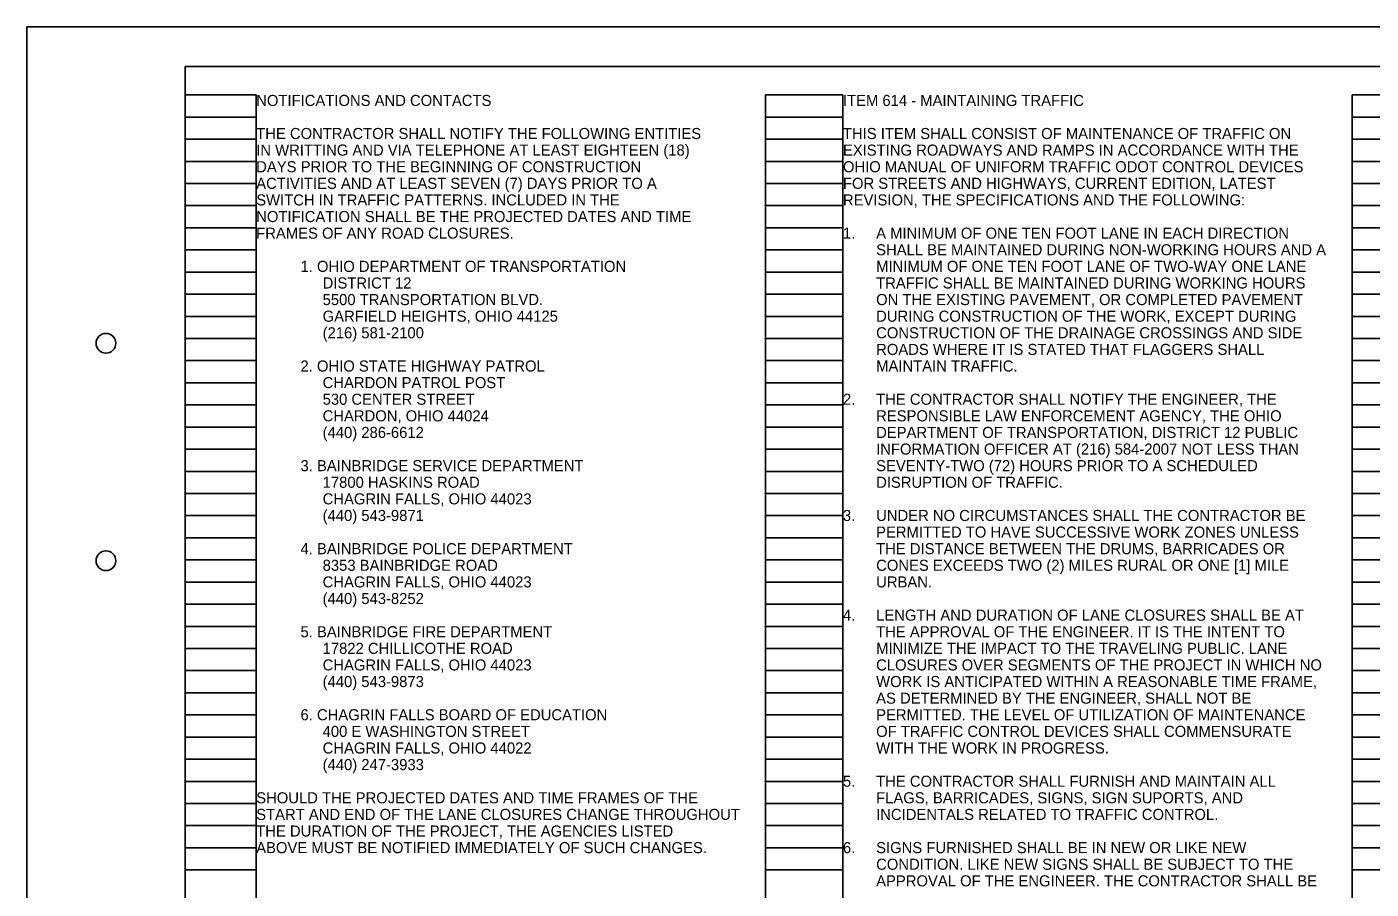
# Model space of a CAD drawing. Extents: x -16.4 to 17.6, y -12.9 to 9.1.
# Drawn here: x -16.37 to 0.63, y -1.81 to 9.09 of the extents above; entities that cross this region are included whole.
import ezdxf

# ---------------------------------------------------------------- set-up
doc = ezdxf.new("R2010")
doc.units = 0
for name, color, linetype in [('SH_Border', 7, 'Continuous'), ('SH_Cut_Line', 7, 'Continuous'), ('SH_Data', 7, 'Continuous'), ('SH_Text', 7, 'Continuous'), ('TX_P_1', 7, 'Continuous')]:
    doc.layers.add(name, color=color, linetype=linetype)

# ---------------------------------------------------------------- blocks, each defined once
blk = doc.blocks.new('4COL')
at = {"layer": 'SH_Data'}
for p, q in [((2, 0.98), (2, 21.14)), ((2, 21.14), (2.9, 21.14)), ((2.9, 0.98), (2.9, 21.14)), ((9.34, 0.98), (9.34, 21.14)), ((9.34, 21.14), (10.32, 21.14)), ((10.32, 0.98), (10.32, 21.14)), ((16.76, 0.98), (16.76, 21.14)), ((16.76, 21.14), (17.74, 21.14)), ((2, 20.86), (2.9, 20.86)), ((9.34, 20.86), (10.32, 20.86)), ((16.76, 20.86), (17.74, 20.86)), ((2, 20.58), (2.9, 20.58)), ((9.34, 20.58), (10.32, 20.58)), ((16.76, 20.58), (17.74, 20.58)), ((2, 20.3), (2.9, 20.3)), ((9.34, 20.3), (10.32, 20.3)), ((16.76, 20.3), (17.74, 20.3)), ((2, 20.02), (2.9, 20.02)), ((9.34, 20.02), (10.32, 20.02)), ((16.76, 20.02), (17.74, 20.02)), ((2, 19.74), (2.9, 19.74)), ((9.34, 19.74), (10.32, 19.74)), ((16.76, 19.74), (17.74, 19.74)), ((2, 19.46), (2.9, 19.46)), ((9.34, 19.46), (10.32, 19.46)), ((16.76, 19.46), (17.74, 19.46)), ((2, 19.18), (2.9, 19.18)), ((9.34, 19.18), (10.32, 19.18)), ((16.76, 19.18), (17.74, 19.18)), ((2, 18.9), (2.9, 18.9)), ((9.34, 18.9), (10.32, 18.9)), ((16.76, 18.9), (17.74, 18.9)), ((2, 18.62), (2.9, 18.62)), ((9.34, 18.62), (10.32, 18.62)), ((16.76, 18.62), (17.74, 18.62)), ((2, 18.34), (2.9, 18.34)), ((9.34, 18.34), (10.32, 18.34)), ((16.76, 18.34), (17.74, 18.34)), ((2, 18.06), (2.9, 18.06)), ((9.34, 18.06), (10.32, 18.06)), ((16.76, 18.06), (17.74, 18.06)), ((2, 17.78), (2.9, 17.78)), ((9.34, 17.78), (10.32, 17.78)), ((16.76, 17.78), (17.74, 17.78)), ((2, 17.5), (2.9, 17.5)), ((9.34, 17.5), (10.32, 17.5)), ((16.76, 17.5), (17.74, 17.5)), ((2, 17.22), (2.9, 17.22)), ((9.34, 17.22), (10.32, 17.22)), ((16.76, 17.22), (17.74, 17.22)), ((2, 16.94), (2.9, 16.94)), ((9.34, 16.94), (10.32, 16.94)), ((16.76, 16.94), (17.74, 16.94)), ((2, 16.66), (2.9, 16.66)), ((9.34, 16.66), (10.32, 16.66)), ((16.76, 16.66), (17.74, 16.66)), ((2, 16.38), (2.9, 16.38)), ((9.34, 16.38), (10.32, 16.38)), ((16.76, 16.38), (17.74, 16.38)), ((2, 16.1), (2.9, 16.1)), ((9.34, 16.1), (10.32, 16.1)), ((16.76, 16.1), (17.74, 16.1)), ((2, 15.82), (2.9, 15.82)), ((9.34, 15.82), (10.32, 15.82)), ((16.76, 15.82), (17.74, 15.82)), ((2, 15.54), (2.9, 15.54)), ((9.34, 15.54), (10.32, 15.54)), ((16.76, 15.54), (17.74, 15.54)), ((2, 15.26), (2.9, 15.26)), ((9.34, 15.26), (10.32, 15.26)), ((16.76, 15.26), (17.74, 15.26)), ((2, 14.98), (2.9, 14.98)), ((9.34, 14.98), (10.32, 14.98)), ((16.76, 14.98), (17.74, 14.98)), ((2, 14.7), (2.9, 14.7)), ((9.34, 14.7), (10.32, 14.7)), ((16.76, 14.7), (17.74, 14.7)), ((2, 14.42), (2.9, 14.42)), ((9.34, 14.42), (10.32, 14.42)), ((16.76, 14.42), (17.74, 14.42)), ((2, 14.14), (2.9, 14.14)), ((9.34, 14.14), (10.32, 14.14)), ((16.76, 14.14), (17.74, 14.14)), ((2, 13.86), (2.9, 13.86)), ((9.34, 13.86), (10.32, 13.86)), ((16.76, 13.86), (17.74, 13.86)), ((2, 13.58), (2.9, 13.58)), ((9.34, 13.58), (10.32, 13.58)), ((16.76, 13.58), (17.74, 13.58)), ((2, 13.3), (2.9, 13.3)), ((9.34, 13.3), (10.32, 13.3)), ((16.76, 13.3), (17.74, 13.3)), ((2, 13.02), (2.9, 13.02)), ((9.34, 13.02), (10.32, 13.02)), ((16.76, 13.02), (17.74, 13.02)), ((2, 12.74), (2.9, 12.74)), ((9.34, 12.74), (10.32, 12.74)), ((16.76, 12.74), (17.74, 12.74)), ((2, 12.46), (2.9, 12.46)), ((9.34, 12.46), (10.32, 12.46)), ((16.76, 12.46), (17.74, 12.46)), ((2, 12.18), (2.9, 12.18)), ((9.34, 12.18), (10.32, 12.18)), ((16.76, 12.18), (17.74, 12.18)), ((2, 11.9), (2.9, 11.9)), ((9.34, 11.9), (10.32, 11.9)), ((16.76, 11.9), (17.74, 11.9)), ((2, 11.62), (2.9, 11.62)), ((9.34, 11.62), (10.32, 11.62)), ((16.76, 11.62), (17.74, 11.62)), ((2, 11.34), (2.9, 11.34)), ((9.34, 11.34), (10.32, 11.34)), ((16.76, 11.34), (17.74, 11.34))]:
    blk.add_line(p, q, dxfattribs=at)

msp = doc.modelspace()

# ---------------------------------------------------------------- linework, layer by layer
at = {"layer": 'SH_Border'}
msp.add_lwpolyline([(-14.371, 8.593), (17.129, 8.593), (17.129, -12.407), (-14.371, -12.407)], close=True, dxfattribs=at)
for centre in [(-15.371, 5.093), (-15.371, 2.343)]:
    msp.add_circle(centre, 0.125, dxfattribs=at)
at = {"layer": 'SH_Cut_Line'}
msp.add_lwpolyline([(-16.371, -12.907), (17.629, -12.907), (17.629, 9.093), (-16.371, 9.093)], close=True, dxfattribs=at)

# ---------------------------------------------------------------- block references
at = {"layer": 'SH_Text'}
msp.add_blockref('4COL', (-16.371, -12.907), dxfattribs=at)

# ---------------------------------------------------------------- texts
for s, p in [('ITEM 614 - MAINTAINING TRAFFIC', (-6.051, 8.093)), ('THIS ITEM SHALL CONSIST OF MAINTENANCE OF TRAFFIC ON ', (-6.051, 7.675)), ('EXISTING ROADWAYS AND RAMPS IN ACCORDANCE WITH THE ', (-6.051, 7.465)), ('OHIO MANUAL OF UNIFORM TRAFFIC ODOT CONTROL DEVICES ', (-6.051, 7.255)), ('FOR STREETS AND HIGHWAYS, CURRENT EDITION, LATEST', (-6.051, 7.045)), ('REVISION, THE SPECIFICATIONS AND THE FOLLOWING:', (-6.051, 6.835)), ('1. ', (-6.051, 6.415)), ('A MINIMUM OF ONE TEN FOOT LANE IN EACH DIRECTION ', (-5.631, 6.415)), ('SHALL BE MAINTAINED DURING NON-WORKING HOURS AND A ', (-5.631, 6.205)), ('MINIMUM OF ONE TEN FOOT LANE OF TWO-WAY ONE LANE ', (-5.631, 5.995)), ('TRAFFIC SHALL BE MAINTAINED DURING WORKING HOURS ', (-5.631, 5.785)), ('ON THE EXISTING PAVEMENT, OR COMPLETED PAVEMENT ', (-5.631, 5.575)), ('DURING CONSTRUCTION OF THE WORK, EXCEPT DURING ', (-5.631, 5.365)), ('CONSTRUCTION OF THE DRAINAGE CROSSINGS AND SIDE ', (-5.631, 5.155)), ('ROADS WHERE IT IS STATED THAT FLAGGERS SHALL ', (-5.631, 4.945)), ('MAINTAIN TRAFFIC.', (-5.631, 4.735)), ('2.', (-6.051, 4.315)), ('THE CONTRACTOR SHALL NOTIFY THE ENGINEER, THE ', (-5.631, 4.315)), ('RESPONSIBLE LAW ENFORCEMENT AGENCY, THE OHIO ', (-5.631, 4.105)), ('DEPARTMENT OF TRANSPORTATION, DISTRICT 12 PUBLIC ', (-5.631, 3.895)), ('INFORMATION OFFICER AT (216) 584-2007 NOT LESS THAN ', (-5.631, 3.685)), ('SEVENTY-TWO (72) HOURS PRIOR TO A SCHEDULED ', (-5.631, 3.475)), ('DISRUPTION OF TRAFFIC.', (-5.631, 3.265)), ('3.', (-6.051, 2.845)), ('UNDER NO CIRCUMSTANCES SHALL THE CONTRACTOR BE ', (-5.631, 2.845)), ('PERMITTED TO HAVE SUCCESSIVE WORK ZONES UNLESS ', (-5.631, 2.635)), ('THE DISTANCE BETWEEN THE DRUMS, BARRICADES OR ', (-5.631, 2.425)), ('CONES EXCEEDS TWO (2) MILES RURAL OR ONE [1] MILE ', (-5.631, 2.215)), ('URBAN.', (-5.631, 2.005)), ('4.', (-6.051, 1.585)), ('LENGTH AND DURATION OF LANE CLOSURES SHALL BE AT ', (-5.631, 1.585)), ('THE APPROVAL OF THE ENGINEER. IT IS THE INTENT TO ', (-5.631, 1.375)), ('MINIMIZE THE IMPACT TO THE TRAVELING PUBLIC. LANE ', (-5.631, 1.165)), ('CLOSURES OVER SEGMENTS OF THE PROJECT IN WHICH NO ', (-5.631, 0.955)), ('WORK IS ANTICIPATED WITHIN A REASONABLE TIME FRAME, ', (-5.631, 0.745)), ('AS DETERMINED BY THE ENGINEER, SHALL NOT BE ', (-5.631, 0.535)), ('PERMITTED. THE LEVEL OF UTILIZATION OF MAINTENANCE ', (-5.631, 0.325)), ('OF TRAFFIC CONTROL DEVICES SHALL COMMENSURATE ', (-5.631, 0.115)), ('WITH THE WORK IN PROGRESS.', (-5.631, -0.095)), ('5.', (-6.051, -0.515)), ('THE CONTRACTOR SHALL FURNISH AND MAINTAIN ALL ', (-5.631, -0.515)), ('FLAGS, BARRICADES, SIGNS, SIGN SUPORTS, AND ', (-5.631, -0.725)), ('INCIDENTALS RELATED TO TRAFFIC CONTROL.', (-5.631, -0.935)), ('6.', (-6.051, -1.355)), ('SIGNS FURNISHED SHALL BE IN NEW OR LIKE NEW ', (-5.631, -1.355)), ('CONDITION. LIKE NEW SIGNS SHALL BE SUBJECT TO THE ', (-5.631, -1.565)), ('APPROVAL OF THE ENGINEER. THE CONTRACTOR SHALL BE ', (-5.631, -1.775))]:
    msp.add_text(s, height=0.14, dxfattribs=at).set_placement(p)
at = {"layer": 'TX_P_1'}
for s, p in [('NOTIFICATIONS AND CONTACTS', (-13.471, 8.093)), ('THE CONTRACTOR SHALL NOTIFY THE FOLLOWING ENTITIES ', (-13.471, 7.675)), ('IN WRITTING AND VIA TELEPHONE AT LEAST EIGHTEEN (18) ', (-13.471, 7.465)), ('DAYS PRIOR TO THE BEGINNING OF CONSTRUCTION ', (-13.471, 7.255)), ('ACTIVITIES AND AT LEAST SEVEN (7) DAYS PRIOR TO A ', (-13.471, 7.045)), ('SWITCH IN TRAFFIC PATTERNS. INCLUDED IN THE ', (-13.471, 6.835)), ('NOTIFICATION SHALL BE THE PROJECTED DATES AND TIME ', (-13.471, 6.625)), ('FRAMES OF ANY ROAD CLOSURES. ', (-13.471, 6.415)), ('1. OHIO DEPARTMENT OF TRANSPORTATION', (-12.911, 5.995)), ('DISTRICT 12', (-12.631, 5.785)), ('5500 TRANSPORTATION BLVD.', (-12.631, 5.575)), ('GARFIELD HEIGHTS, OHIO 44125', (-12.631, 5.365)), ('(216) 581-2100', (-12.631, 5.155)), ('2. OHIO STATE HIGHWAY PATROL', (-12.911, 4.735)), ('CHARDON PATROL POST', (-12.631, 4.525)), ('530 CENTER STREET', (-12.631, 4.315)), ('CHARDON, OHIO 44024', (-12.631, 4.105)), ('(440) 286-6612', (-12.631, 3.895)), ('3. BAINBRIDGE SERVICE DEPARTMENT', (-12.911, 3.475)), ('17800 HASKINS ROAD', (-12.631, 3.265)), ('CHAGRIN FALLS, OHIO 44023', (-12.631, 3.055)), ('(440) 543-9871', (-12.631, 2.845)), ('4. BAINBRIDGE POLICE DEPARTMENT', (-12.911, 2.425)), ('8353 BAINBRIDGE ROAD', (-12.631, 2.215)), ('CHAGRIN FALLS, OHIO 44023', (-12.631, 2.005)), ('(440) 543-8252', (-12.631, 1.795)), ('5. BAINBRIDGE FIRE DEPARTMENT', (-12.911, 1.375)), ('17822 CHILLICOTHE ROAD', (-12.631, 1.165)), ('CHAGRIN FALLS, OHIO 44023', (-12.631, 0.955)), ('(440) 543-9873', (-12.631, 0.745)), ('6. CHAGRIN FALLS BOARD OF EDUCATION', (-12.911, 0.325)), ('400 E WASHINGTON STREET', (-12.631, 0.115)), ('CHAGRIN FALLS, OHIO 44022', (-12.631, -0.095)), ('(440) 247-3933', (-12.631, -0.305)), ('SHOULD THE PROJECTED DATES AND TIME FRAMES OF THE ', (-13.471, -0.725)), ('START AND END OF THE LANE CLOSURES CHANGE THROUGHOUT ', (-13.471, -0.935)), ('THE DURATION OF THE PROJECT, THE AGENCIES LISTED ', (-13.471, -1.145)), ('ABOVE MUST BE NOTIFIED IMMEDIATELY OF SUCH CHANGES.', (-13.471, -1.355))]:
    msp.add_text(s, height=0.14, dxfattribs=at).set_placement(p)

doc.saveas('drawing.dxf')
